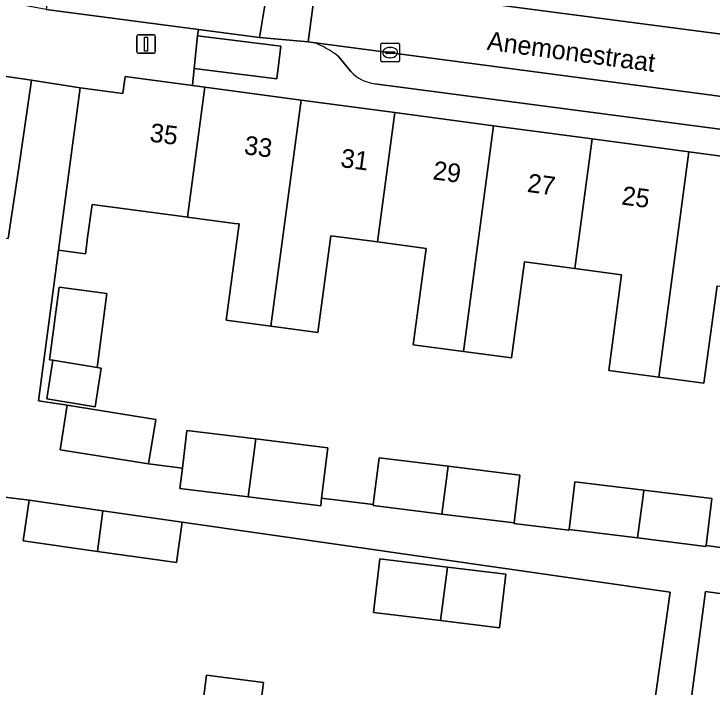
# Model space of a CAD drawing. Extents: x 161838 to 162344, y 381620 to 382160.
# Drawn here: x 161912.46 to 161949.93, y 381672.51 to 381708.64 of the extents above; entities that cross this region are included whole.
import ezdxf

# ---------------------------------------------------------------- set-up
doc = ezdxf.new("R2010")
doc.units = 0
for name, color, linetype in [('IMGEO_Erf', 7, 'Continuous'), ('IMGEO_Kolk', 7, 'Continuous'), ('IMGEO_Lichtmast', 7, 'Continuous'), ('IMGEO_Openbare_ruimte_label', 7, 'Continuous'), ('IMGEO_Pand', 7, 'Continuous'), ('IMGEO_Pand_nummerreeks', 7, 'Continuous'), ('IMGEO_Parkeervlak_open', 7, 'Continuous'), ('IMGEO_Rijbaan_lokaal_open', 7, 'Continuous'), ('IMGEO_Voetpad_open', 7, 'Continuous')]:
    doc.layers.add(name, color=color, linetype=linetype)

msp = doc.modelspace()

# ---------------------------------------------------------------- linework, layer by layer
at = {"layer": 'IMGEO_Erf'}
for points in [[(161950.202, 381694.057), (161949.503, 381688.82), (161947.077, 381689.144), (161944.394, 381689.502), (161945.079, 381694.639), (161942.569, 381694.974), (161939.864, 381695.335), (161939.177, 381690.183), (161936.585, 381690.529), (161933.893, 381690.888), (161934.582, 381696.057), (161931.979, 381696.404), (161929.472, 381696.739), (161928.779, 381691.545), (161926.254, 381691.882), (161923.85, 381692.203), (161924.54, 381697.37), (161924.292, 381697.403), (161923.371, 381697.526), (161921.775, 381697.739), (161921.674, 381697.752), (161916.648, 381698.422), (161916.395, 381696.52), (161916.368, 381696.321), (161916.295, 381695.776), (161914.853, 381695.968), (161913.774, 381687.885), (161915.322, 381687.637), (161920.069, 381686.876), (161919.686, 381684.49), (161921.498, 381684.268), (161921.745, 381686.286), (161925.448, 381685.832), (161929.308, 381685.359), (161928.976, 381682.643), (161931.748, 381682.303), (161932.056, 381684.82), (161935.764, 381684.366), (161939.619, 381683.893), (161939.304, 381681.325), (161939.3, 381681.291), (161942.255, 381680.93), (161942.259, 381680.963), (161942.553, 381683.364), (161942.573, 381683.53), (161946.269, 381683.077), (161949.925, 381682.628), (161949.616, 381680.114), (161951.047, 381679.913)], [(161946.636, 381670.142), (161947.691, 381677.6), (161921.491, 381681.359), (161921.181, 381679.202), (161916.934, 381679.797), (161912.958, 381680.354), (161913.27, 381682.538), (161909.889, 381682.955)], [(161972.382, 381674.573), (161969.95, 381674.905), (161969.694, 381672.71), (161965.529, 381673.268), (161961.422, 381673.819), (161961.689, 381676.019), (161960.325, 381676.197), (161960.252, 381675.497), (161960.22, 381675.191), (161959.973, 381672.833), (161954.676, 381673.537), (161954.833, 381674.705), (161950.722, 381675.252), (161950.995, 381677.449), (161949.581, 381677.64), (161948.005, 381665.745)], [(161922.395, 381670.091), (161922.799, 381673.154), (161925.854, 381672.751), (161925.454, 381669.719)]]:
    msp.add_lwpolyline(points, dxfattribs=at)
for points in [[(161916.923, 381689.673), (161917.143, 381689.638), (161916.81, 381687.563), (161914.218, 381687.979), (161914.551, 381690.054), (161914.363, 381690.084), (161914.883, 381693.975), (161917.451, 381693.633)], [(161932.104, 381679.387), (161935.735, 381678.948), (161938.873, 381678.569), (161938.527, 381675.698), (161935.357, 381676.081), (161931.757, 381676.515)]]:
    msp.add_lwpolyline(points, close=True, dxfattribs=at)
at = {"layer": 'IMGEO_Kolk'}
for p, q in [((161932.153, 381706.146), (161932.153, 381706.998)), ((161932.228, 381707.072), (161933.08, 381707.072)), ((161933.154, 381706.998), (161933.154, 381706.146)), ((161932.455, 381706.615), (161932.853, 381706.615)), ((161932.641, 381706.852), (161932.666, 381706.852)), ((161932.412, 381706.566), (161932.412, 381706.578)), ((161932.85, 381706.529), (161932.452, 381706.529)), ((161932.664, 381706.292), (161932.639, 381706.292)), ((161932.896, 381706.578), (161932.896, 381706.566)), ((161933.08, 381706.072), (161932.228, 381706.072))]:
    msp.add_line(p, q, dxfattribs=at)
for points in [[(161932.153, 381706.146), (161932.153, 381706.998)], [(161932.228, 381707.072), (161933.08, 381707.072)], [(161933.154, 381706.998), (161933.154, 381706.146)], [(161933.08, 381706.072), (161932.228, 381706.072)]]:
    msp.add_lwpolyline(points, dxfattribs=at)
for centre, radius, start, end in [((161932.23, 381706.996), 0.0765, 91.552, 178.448), ((161932.23, 381706.996), 0.0765, 91.552, 178.448), ((161933.078, 381706.996), 0.0765, 1.552, 88.448), ((161933.078, 381706.996), 0.0765, 1.552, 88.448), ((161932.452, 381706.575), 0.0403, 85.8775, 175.7526), ((161932.857, 381706.577), 0.0386, 1.7309, 96.639), ((161932.449, 381706.565), 0.0366, 178.938, 274.7102), ((161932.853, 381706.572), 0.043, 264.8664, 352.4533), ((161932.23, 381706.148), 0.0765, 181.552, 268.448), ((161932.23, 381706.148), 0.0765, 181.552, 268.448), ((161933.078, 381706.148), 0.0765, 271.552, 358.448), ((161933.078, 381706.148), 0.0765, 271.552, 358.448)]:
    msp.add_arc(centre, radius, start, end, dxfattribs=at)
for centre, major_axis, ratio, start_param, end_param in [((161932.64, 381706.572), (-0.387, 0.002), 0.722429, 4.712389, 7.853982), ((161932.665, 381706.572), (-0.39, 0.002), 0.717154, 1.570796, 4.712389)]:
    msp.add_ellipse(centre, major_axis=major_axis, ratio=ratio, start_param=start_param, end_param=end_param, dxfattribs=at)
at = {"layer": 'IMGEO_Lichtmast'}
for p, q in [((161919.053, 381706.631), (161919.053, 381707.431)), ((161919.053, 381707.431), (161919.053, 381706.631)), ((161919.153, 381707.531), (161919.943, 381707.531)), ((161919.943, 381707.531), (161919.153, 381707.531)), ((161920.043, 381707.431), (161920.043, 381706.631)), ((161920.043, 381706.631), (161920.043, 381707.431)), ((161919.943, 381706.531), (161919.153, 381706.531)), ((161919.153, 381706.531), (161919.943, 381706.531))]:
    msp.add_line(p, q, dxfattribs=at)
msp.add_lwpolyline([(161919.473, 381707.406), (161919.623, 381707.406), (161919.623, 381706.656), (161919.473, 381706.656), (161919.473, 381707.406)], dxfattribs=at)
for centre, start, end in [((161919.153, 381707.431), 90, 180), ((161919.153, 381707.431), 90, 180), ((161919.943, 381707.431), 0, 90), ((161919.943, 381707.431), 360, 90), ((161919.153, 381706.631), 180, 270), ((161919.153, 381706.631), 180, 270), ((161919.943, 381706.631), 270, 0), ((161919.943, 381706.631), 270, 0)]:
    msp.add_arc(centre, 0.1, start, end, dxfattribs=at)
at = {"layer": 'IMGEO_Pand'}
for points in [[(161905.591, 381692.011), (161908.004, 381691.658), (161908.799, 381697.088), (161912.155, 381696.597), (161912.675, 381700.146), (161913.399, 381705.093), (161907.63, 381705.938)], [(161922.703, 381704.711), (161922.044, 381704.799), (161918.428, 381705.281), (161918.308, 381704.376), (161916.016, 381704.682), (161915.355, 381699.726), (161914.853, 381695.968), (161916.295, 381695.776), (161916.368, 381696.321), (161916.395, 381696.52), (161916.648, 381698.422), (161921.674, 381697.752), (161921.775, 381697.739)], [(161927.871, 381704.021), (161922.703, 381704.711), (161921.775, 381697.739), (161923.371, 381697.526), (161924.292, 381697.403), (161924.54, 381697.37), (161923.85, 381692.203), (161926.254, 381691.882)], [(161931.979, 381696.404), (161932.904, 381703.349), (161927.871, 381704.021), (161926.254, 381691.882), (161928.779, 381691.545), (161929.472, 381696.739)], [(161938.199, 381702.643), (161932.904, 381703.349), (161931.979, 381696.404), (161934.582, 381696.057), (161933.893, 381690.888), (161936.585, 381690.529)], [(161938.199, 381702.643), (161936.585, 381690.529), (161939.177, 381690.183), (161939.864, 381695.335), (161942.569, 381694.974), (161943.496, 381701.936)], [(161947.077, 381689.144), (161948.689, 381701.243), (161943.496, 381701.936), (161942.569, 381694.974), (161945.079, 381694.639), (161944.394, 381689.502)], [(161947.077, 381689.144), (161949.503, 381688.82), (161950.202, 381694.057), (161952.976, 381693.687), (161953.23, 381695.593), (161953.892, 381700.549), (161948.689, 381701.243)], [(161914.551, 381690.054), (161916.923, 381689.673), (161917.451, 381693.633), (161914.883, 381693.975), (161914.363, 381690.084)], [(161916.923, 381689.673), (161914.551, 381690.054), (161914.218, 381687.979), (161916.81, 381687.563), (161917.143, 381689.638)], [(161914.939, 381685.25), (161919.686, 381684.49), (161920.069, 381686.876), (161915.322, 381687.637)], [(161925.448, 381685.832), (161921.745, 381686.286), (161921.498, 381684.268), (161921.363, 381683.165), (161925.033, 381682.715)], [(161929.308, 381685.359), (161925.448, 381685.832), (161925.033, 381682.715), (161928.926, 381682.238), (161928.976, 381682.643)], [(161935.764, 381684.366), (161932.056, 381684.82), (161931.748, 381682.303), (161931.742, 381682.251), (161935.422, 381681.8)], [(161939.619, 381683.893), (161935.764, 381684.366), (161935.422, 381681.8), (161939.304, 381681.325)], [(161946.269, 381683.077), (161942.573, 381683.53), (161942.553, 381683.364), (161942.259, 381680.963), (161945.927, 381680.514), (161946.193, 381682.509), (161946.247, 381682.912)], [(161946.269, 381683.077), (161946.247, 381682.912), (161946.193, 381682.509), (161945.927, 381680.514), (161949.61, 381680.062), (161949.616, 381680.114), (161949.925, 381682.628)], [(161917.232, 381681.97), (161913.27, 381682.538), (161912.958, 381680.354), (161916.934, 381679.797)], [(161917.232, 381681.97), (161916.934, 381679.797), (161921.181, 381679.202), (161921.491, 381681.359)], [(161935.357, 381676.081), (161935.735, 381678.948), (161932.104, 381679.387), (161931.757, 381676.515)], [(161935.357, 381676.081), (161938.527, 381675.698), (161938.873, 381678.569), (161935.735, 381678.948)], [(161928.56, 381667.429), (161923.841, 381668.05), (161924.085, 381669.9), (161925.454, 381669.719), (161925.854, 381672.751), (161922.799, 381673.154), (161922.395, 381670.091), (161922.667, 381670.055), (161922.41, 381668.169), (161922.127, 381666.023), (161921.474, 381661.065), (161927.614, 381660.256)]]:
    msp.add_lwpolyline(points, close=True, dxfattribs=at)
at = {"layer": 'IMGEO_Parkeervlak_open'}
for points in [[(161928.816, 381710.405), (161954.008, 381707.086), (161955.333, 381706.911)], [(161954.92, 381703.622), (161953.57, 381703.801), (161928.51, 381707.121)], [(161929.878, 381706.358), (161930.543, 381705.562)], [(161931.829, 381704.897), (161951.583, 381702.305)]]:
    msp.add_lwpolyline(points, dxfattribs=at)
msp.add_lwpolyline([(161926.573, 381705.169), (161926.777, 381706.91), (161922.319, 381707.479), (161922.127, 381705.725)], close=True, dxfattribs=at)
for centre, radius, start, end in [((161927.015, 381702.832), 4.542, 50.9195, 70.7794), ((161932.081, 381706.96), 2.078, 222.2704, 263.042)]:
    msp.add_arc(centre, radius, start, end, dxfattribs=at)
at = {"layer": 'IMGEO_Rijbaan_lokaal_open'}
msp.add_lwpolyline([(161920.785, 381714.418), (161917.929, 381715.13), (161915.172, 381715.818), (161914.683, 381712.406), (161914.467, 381710.894), (161914.179, 381708.883), (161922.367, 381707.809), (161925.644, 381707.379), (161925.94, 381709.21), (161926.223, 381710.961), (161923.709, 381711.274)], dxfattribs=at)
for points in [[(161925.644, 381707.379), (161928.26, 381707.154), (161928.47, 381708.756), (161928.688, 381710.422), (161928.816, 381710.405), (161926.223, 381710.961), (161925.94, 381709.21)], [(161954.008, 381707.086), (161928.816, 381710.405), (161928.688, 381710.422), (161928.47, 381708.756), (161928.26, 381707.154), (161928.51, 381707.121), (161953.57, 381703.801)]]:
    msp.add_lwpolyline(points, close=True, dxfattribs=at)
at = {"layer": 'IMGEO_Voetpad_open'}
for points in [[(161867.479, 381715.184), (161866.911, 381711.167), (161868.259, 381712.301), (161889.701, 381708.562), (161890.618, 381708.428), (161896.772, 381707.527), (161902.202, 381706.732), (161907.63, 381705.938), (161913.399, 381705.093), (161916.016, 381704.682), (161918.308, 381704.376), (161918.428, 381705.281), (161922.044, 381704.799), (161922.127, 381705.725), (161922.319, 381707.479)], [(161922.319, 381707.479), (161922.367, 381707.809), (161914.179, 381708.883), (161911.754, 381709.336), (161909.378, 381709.658)], [(161928.51, 381707.121), (161928.26, 381707.154), (161925.644, 381707.379), (161922.367, 381707.809), (161922.319, 381707.479), (161926.777, 381706.91), (161926.573, 381705.169), (161922.127, 381705.725), (161922.044, 381704.799), (161922.703, 381704.711), (161927.871, 381704.021), (161932.904, 381703.349), (161938.199, 381702.643), (161943.496, 381701.936), (161948.689, 381701.243), (161953.892, 381700.549), (161955.123, 381700.39), (161986.324, 381696.353)], [(161930.543, 381705.562), (161929.878, 381706.358)], [(161951.047, 381679.913), (161949.616, 381680.114), (161949.61, 381680.062), (161945.927, 381680.514), (161942.259, 381680.963), (161942.255, 381680.93), (161939.3, 381681.291), (161939.304, 381681.325), (161935.422, 381681.8), (161931.742, 381682.251), (161931.748, 381682.303), (161928.976, 381682.643), (161928.926, 381682.238), (161925.033, 381682.715), (161921.363, 381683.165), (161921.498, 381684.268), (161919.686, 381684.49), (161914.939, 381685.25), (161915.322, 381687.637), (161913.774, 381687.885), (161914.853, 381695.968), (161915.355, 381699.726), (161916.016, 381704.682), (161913.399, 381705.093), (161912.675, 381700.146), (161912.155, 381696.597)], [(161951.583, 381702.305), (161931.829, 381704.897)], [(161909.889, 381682.955), (161913.27, 381682.538), (161917.232, 381681.97), (161921.491, 381681.359), (161947.691, 381677.6), (161946.636, 381670.142), (161945.913, 381665.031), (161945.579, 381662.88), (161944.926, 381657.922), (161944.516, 381654.835), (161946.525, 381654.568), (161946.833, 381656.89), (161947.479, 381661.775), (161948.005, 381665.745), (161949.581, 381677.64), (161950.995, 381677.449), (161955.128, 381676.892), (161959.253, 381676.337), (161960.325, 381676.197), (161961.689, 381676.019), (161965.824, 381675.461), (161969.95, 381674.905), (161972.382, 381674.573)]]:
    msp.add_lwpolyline(points, dxfattribs=at)
for centre, radius, start, end in [((161927.015, 381702.832), 4.542, 50.9195, 70.7794), ((161932.081, 381706.96), 2.078, 222.2704, 263.042)]:
    msp.add_arc(centre, radius, start, end, dxfattribs=at)

# ---------------------------------------------------------------- texts
at = {"layer": 'IMGEO_Openbare_ruimte_label'}
msp.add_text('Anemonestraat', height=1, rotation=352.4129, dxfattribs=at).set_placement((161937.819, 381706.729))
at = {"layer": 'IMGEO_Pand_nummerreeks'}
for s, rotation, p in [('35', 352.4026, (161919.709, 381701.801)), ('33', 352.4026, (161924.775, 381701.125)), ('31', 352.3999, (161929.953, 381700.433)), ('29', 352.3999, (161934.907, 381699.772)), ('27', 352.3999, (161939.974, 381699.096)), ('25', 352.3999, (161945.04, 381698.42))]:
    msp.add_text(s, height=1, rotation=rotation, dxfattribs=at).set_placement(p)

doc.saveas('drawing.dxf')
